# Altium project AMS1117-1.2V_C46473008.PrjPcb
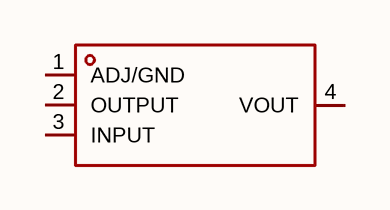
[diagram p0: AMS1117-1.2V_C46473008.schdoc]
1 sheet, 1 parts. Net scope: global (net labels, ports and power ports of the same name join across sheets).

## Sheet AMS1117-1.2V_C46473008.schdoc
size 127 x 101 mm

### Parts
U?  ams1117-1.2v_c46473008  [SOT-223-4_L6.5-W3.5-P2.30-LS7.0-BR]  (value not drawn)

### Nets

Not connected (* = marked no-connect by the designer): U? 1(ADJ/GND) 2(OUTPUT) 3(INPUT) 4(VOUT)

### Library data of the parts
U? = ams1117-1.2v_c46473008: 输出极性:正极;工作电压:18V;输出电压:1.2V;输出电流:1A;电源纹波抑制比(PSRR):-;输出类型:固定;; Manufacturer: TECH PUBLIC(台舟); AddInBom: yes; ModelId: 925194bf9823436183a3e0b978a8d076; ModelName: SOT-223-4P_L6.5-W3.5-H1.6-LS7.0-P2.30; ModelTransform: 279.89794,255.905,0,180,0,0,-0.0005,-0.0005,0; Output Configuration: 正极; Voltage - Supply: 18V; Output Voltage: 1.2V; Output Current: 1A; Voltage Dropout: 1.26V@(1A); standby current: 4mA; Output Type: 固定; Number of Outputs: 1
